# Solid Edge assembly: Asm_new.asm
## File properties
Author: CADSoft
Template: Sync Iso Assembly.asm
Last saved by: CADCIM
Revision: 11
Application: Solid Edge
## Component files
casting_new.par
brass_new.par
cap_1224.par
Bolt.par
Nut.par
Lock Nut.par
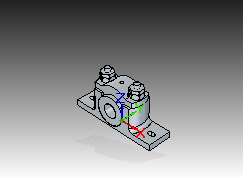
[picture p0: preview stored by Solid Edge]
